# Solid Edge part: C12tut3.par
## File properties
Author: Ashutosh-CADCIM
Template: ansi inch part.par
Last saved by: Rajat Kamboj
Revision: 3
Application: Solid Edge
Accuracy: 0.990
Username: Ashutosh-CADCIM
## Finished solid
Body 1: solid body, 12 faces, 16 edges, 6 vertices.
  Faces by surface: plane 8, cylinder 4
  Edges by curve: circle 8, line 7, ellipse 1
Bounding box of the edges (mm): 31.750 x 82.478 x 31.750, from (-15.875, -77.9793, -15.875) to (15.875, 4.4987, 15.875).
Cylindrical faces by radius (mm): R5.5944 x1, R6.35 x1, R7.9375 x1, R15.875 x1
Planar faces by outward normal: +x 1, +y 1, -x 1, -y 4, oblique 1
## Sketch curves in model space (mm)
line (-22.318, -0.2404, 12.6982) -> (-22.2829, -4.9679, 7.9011)
line (-22.2618, -77.9738, 5.0232) -> (-22.2673, -0.1897, 5.7686)
line (-22.1798, -77.8918, -6.1649) -> (-22.1842, -0.1066, -5.5759)
line (-22.2202, -89.5716, -0.6561) -> (-22.2258, 15.4021, 0.1128)
line (-22.2678, -68.4546, 5.8486) -> (-22.2673, -77.9793, 5.7788)
line (-22.2673, -77.9793, 5.7788) -> (-22.1743, -77.8863, -6.9205)
line (-22.1748, -68.3616, -6.8507) -> (-22.1743, -77.8863, -6.9205)
line (-22.3413, -0.2637, 15.8731) -> (-22.1087, -0.0311, -15.8752)
line (-22.3415, 4.4987, 15.908) -> (-22.3413, -0.2637, 15.8731)
line (-22.3415, 4.4987, 15.908) -> (-22.109, 4.7312, -15.8403)
line (-22.109, 4.7312, -15.8403) -> (-22.1087, -0.0311, -15.8752)
line (-22.1669, -0.0893, -7.9382) -> (-22.1632, -68.3499, -8.4381)
line (-22.2831, -0.2055, 7.936) -> (-22.2795, -68.4662, 7.436)
line (-22.2795, -68.4662, 7.436) -> (-22.1632, -68.3499, -8.4381)
line (0, 0, 22.225) -> (0, 0, -22.225)
line (22.225, 0, 0) -> (-22.225, 0, 0)
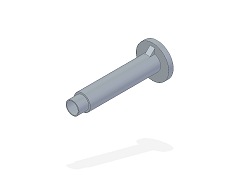
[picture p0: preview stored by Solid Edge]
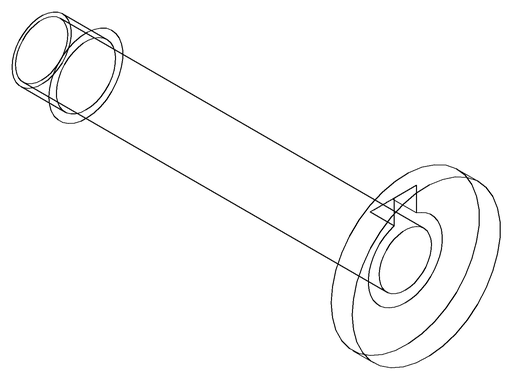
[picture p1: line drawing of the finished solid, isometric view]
